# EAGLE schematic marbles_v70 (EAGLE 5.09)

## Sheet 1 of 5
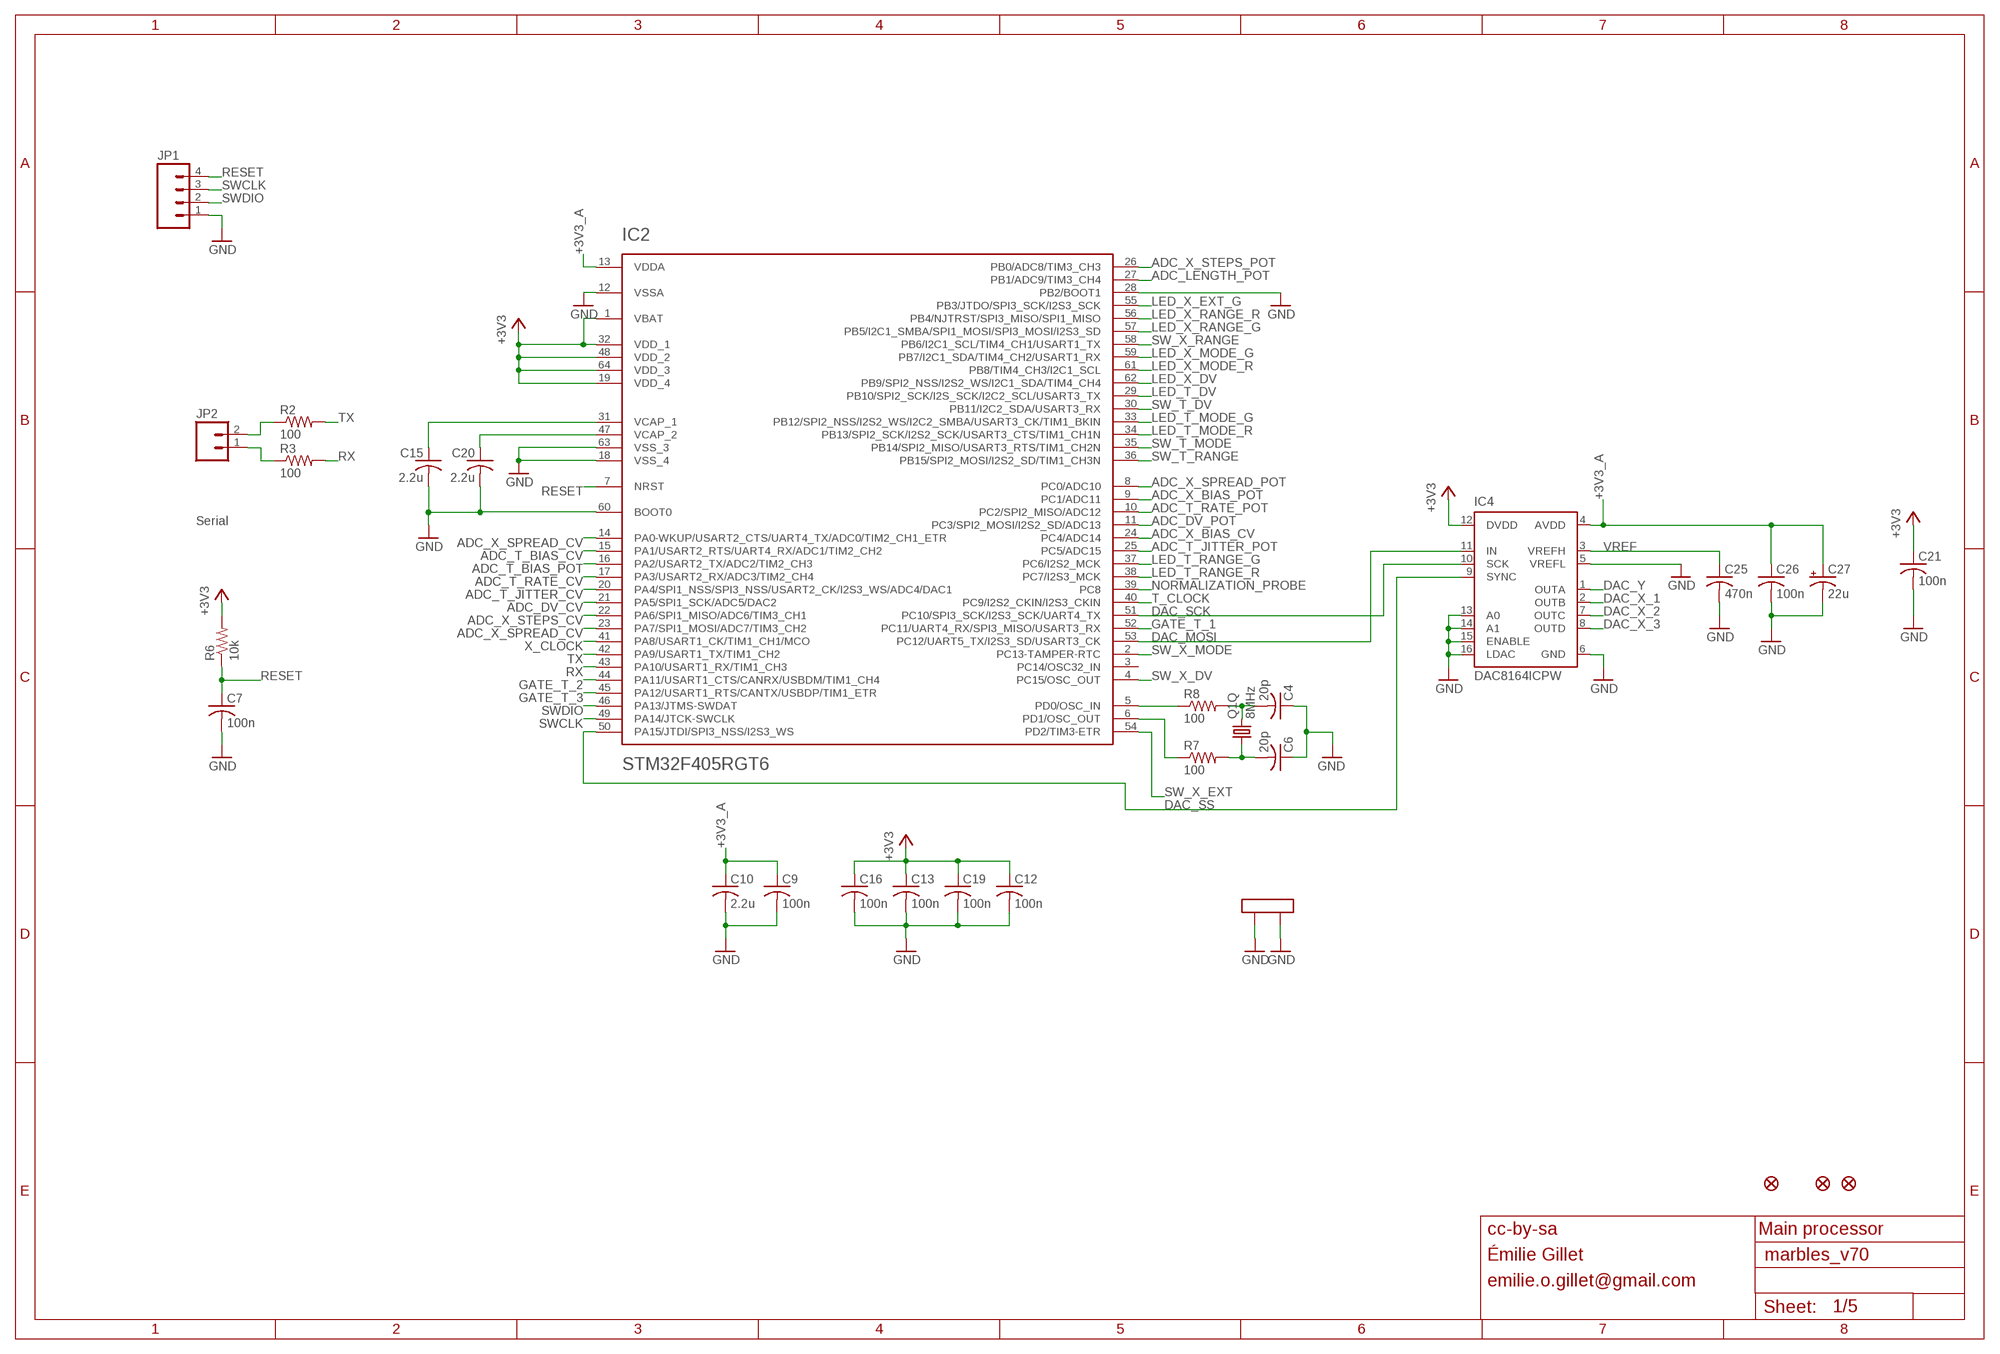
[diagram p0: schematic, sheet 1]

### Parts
C4  20p  C-USC0402  [C0402]
C6  20p  C-USC0402  [C0402]
C7  100n  C-USC0402  [C0402]
C9  100n  C-USC0402  [C0402]
C10  2.2u  C-USC0805  [C0805]
C12  100n  C-USC0402  [C0402]
C13  100n  C-USC0402  [C0402]
C15  2.2u  C-USC0805  [C0805]
C16  100n  C-USC0402  [C0402]
C19  100n  C-USC0402  [C0402]
C20  2.2u  C-USC0805  [C0805]
C21  100n  C-USC0402  [C0402]
C25  470n  C-USC0402  [C0402]
C26  100n  C-USC0402  [C0402]
C27  22u  CPOL-USC  [PANASONIC_C]
F1  FIDUCIAL1X2  [FIDUCIAL-1X2]
F2  FIDUCIAL1X2  [FIDUCIAL-1X2]
F3  FIDUCIAL1X2  [FIDUCIAL-1X2]
IC2  STM32F405RGT6  STM32F20X  [TQFP-10X10-64]
IC4  DAC8164ICPW  DAC8564  [SOP65P640X110-16N]
JP1  M04PTH  [1X04]
JP2  M02PTH  [1X02]
Q1  8MHz  CRYSTAL  [CTS406]
R2  100  R-US_R0402  [R0402]
R3  100  R-US_R0402  [R0402]
R6  10k  R-US_R0402  [R0402]
R7  100  R-US_R0402  [R0402]
R8  100  R-US_R0402  [R0402]

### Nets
+3V3: C12.1 C13.1 C16.1 C19.1 C21.1 IC2.1(VBAT) IC2.19(VDD_4) IC2.32(VDD_1) IC2.48(VDD_2) IC2.64(VDD_3) IC4.12(DVDD) R6.2 ; also sheet 3,5
+3V3_A: C9.1 C10.1 C26.1 C27.+ IC2.13(VDDA) IC4.4(AVDD) ; also sheet 2,3,5
ADC_DV_CV: IC2.21(PA5/SPI1_SCK/ADC5/DAC2) ; also sheet 3
ADC_DV_POT: IC2.11(PC3/SPI2_MOSI/I2S2_SD/ADC13) ; also sheet 2
ADC_LENGTH_POT: IC2.27(PB1/ADC9/TIM3_CH4) ; also sheet 2
ADC_T_BIAS_CV: IC2.15(PA1/USART2_RTS/UART4_RX/ADC1/TIM2_CH2) ; also sheet 3
ADC_T_BIAS_POT: IC2.16(PA2/USART2_TX/ADC2/TIM2_CH3) ; also sheet 2
ADC_T_JITTER_CV: IC2.20(PA4/SPI1_NSS/SPI3_NSS/USART2_CK/I2S3_WS/ADC4/DAC1) ; also sheet 3
ADC_T_JITTER_POT: IC2.25(PC5/ADC15) ; also sheet 2
ADC_T_RATE_CV: IC2.17(PA3/USART2_RX/ADC3/TIM2_CH4) ; also sheet 3
ADC_T_RATE_POT: IC2.10(PC2/SPI2_MISO/ADC12) ; also sheet 2
ADC_X_BIAS_CV: IC2.24(PC4/ADC14) ; also sheet 3
ADC_X_BIAS_POT: IC2.9(PC1/ADC11) ; also sheet 2
ADC_X_SPREAD_CV: IC2.14(PA0-WKUP/USART2_CTS/UART4_TX/ADC0/TIM2_CH1_ETR) IC2.23(PA7/SPI1_MOSI/ADC7/TIM3_CH2) ; also sheet 3
ADC_X_SPREAD_POT: IC2.8(PC0/ADC10) ; also sheet 2
ADC_X_STEPS_CV: IC2.22(PA6/SPI1_MISO/ADC6/TIM3_CH1) ; also sheet 3
ADC_X_STEPS_POT: IC2.26(PB0/ADC8/TIM3_CH3) ; also sheet 2
DAC_MOSI: IC2.53(PC12/UART5_TX/I2S3_SD/USART3_CK) IC4.11(IN)
DAC_SCK: IC2.51(PC10/SPI3_SCK/I2S3_SCK/UART4_TX) IC4.10(SCK)
DAC_SS: IC2.50(PA15/JTDI/SPI3_NSS/I2S3_WS) IC4.9(SYNC)
DAC_X_1: IC4.2(OUTB) ; also sheet 4
DAC_X_2: IC4.7(OUTC) ; also sheet 4
DAC_X_3: IC4.8(OUTD) ; also sheet 4
DAC_Y: IC4.1(OUTA) ; also sheet 4
GATE_T_1: IC2.52(PC11/UART4_RX/SPI3_MISO/USART3_RX) ; also sheet 4
GATE_T_2: IC2.44(PA11/USART1_CTS/CANRX/USBDM/TIM1_CH4) ; also sheet 4
GATE_T_3: IC2.45(PA12/USART1_RTS/CANTX/USBDP/TIM1_ETR) ; also sheet 4
GND: C4.1 C6.1 C7.2 C9.2 C10.2 C12.2 C13.2 C15.2 C16.2 C19.2 C20.2 C21.2 C25.2 C26.2 C27.- IC2.12(VSSA) IC2.18(VSS_4) IC2.28(PB2/BOOT1) IC2.60(BOOT0) IC2.63(VSS_3) IC4.5(VREFL) IC4.6(GND) IC4.13(A0) IC4.14(A1) IC4.15(ENABLE) IC4.16(LDAC) JP1.1 Q1.2(LID1) Q1.4(LID2) ; also sheet 2,3,4,5
LED_T_DV: IC2.29(PB10/SPI2_SCK/I2S_SCK/I2C2_SCL/USART3_TX) ; also sheet 2
LED_T_MODE_G: IC2.33(PB12/SPI2_NSS/I2S2_WS/I2C2_SMBA/USART3_CK/TIM1_BKIN) ; also sheet 2
LED_T_MODE_R: IC2.34(PB13/SPI2_SCK/I2S2_SCK/USART3_CTS/TIM1_CH1N) ; also sheet 2
LED_T_RANGE_G: IC2.37(PC6/I2S2_MCK) ; also sheet 2
LED_T_RANGE_R: IC2.38(PC7/I2S3_MCK) ; also sheet 2
LED_X_DV: IC2.62(PB9/SPI2_NSS/I2S2_WS/I2C1_SDA/TIM4_CH4) ; also sheet 2
LED_X_EXT_G: IC2.55(PB3/JTDO/SPI3_SCK/I2S3_SCK) ; also sheet 2
LED_X_MODE_G: IC2.59(PB7/I2C1_SDA/TIM4_CH2/USART1_RX) ; also sheet 2
LED_X_MODE_R: IC2.61(PB8/TIM4_CH3/I2C1_SCL) ; also sheet 2
LED_X_RANGE_G: IC2.57(PB5/I2C1_SMBA/SPI1_MOSI/SPI3_MOSI/I2S3_SD) ; also sheet 2
LED_X_RANGE_R: IC2.56(PB4/NJTRST/SPI3_MISO/SPI1_MISO) ; also sheet 2
N$7: IC2.6(PD1/OSC_OUT) R7.1
N$8: IC2.5(PD0/OSC_IN) R8.1
N$13: C20.1 IC2.47(VCAP_2)
N$19: C15.1 IC2.31(VCAP_1)
N$33: JP2.2 R2.1
N$51: JP2.1 R3.1
N$62: C4.2 Q1.3 R8.2
N$65: C6.2 Q1.1 R7.2
NORMALIZATION_PROBE: IC2.39(PC8) ; also sheet 3
RESET: C7.1 IC2.7(NRST) JP1.4 R6.1
RX: IC2.43(PA10/USART1_RX/TIM1_CH3) R3.2
SW_T_DV: IC2.30(PB11/I2C2_SDA/USART3_RX) ; also sheet 2
SW_T_MODE: IC2.35(PB14/SPI2_MISO/USART3_RTS/TIM1_CH2N) ; also sheet 2
SW_T_RANGE: IC2.36(PB15/SPI2_MOSI/I2S2_SD/TIM1_CH3N) ; also sheet 2
SW_X_DV: IC2.4(PC15/OSC_OUT) ; also sheet 2
SW_X_EXT: IC2.54(PD2/TIM3-ETR) ; also sheet 2
SW_X_MODE: IC2.2(PC13-TAMPER-RTC) ; also sheet 2
SW_X_RANGE: IC2.58(PB6/I2C1_SCL/TIM4_CH1/USART1_TX) ; also sheet 2
SWCLK: IC2.49(PA14/JTCK-SWCLK) JP1.3
SWDIO: IC2.46(PA13/JTMS-SWDAT) JP1.2
T_CLOCK: IC2.40(PC9/I2S2_CKIN/I2S3_CKIN) ; also sheet 3
TX: IC2.42(PA9/USART1_TX/TIM1_CH2) R2.2
VREF: C25.1 IC4.3(VREFH) ; also sheet 4
X_CLOCK: IC2.41(PA8/USART1_CK/TIM1_CH1/MCO) ; also sheet 3
Unconnected: IC2.3(PC14/OSC32_IN)

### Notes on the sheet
- Serial
- cc-by-sa | Main processor
- Émilie Gillet
- emilie.o.gillet@gmail.com

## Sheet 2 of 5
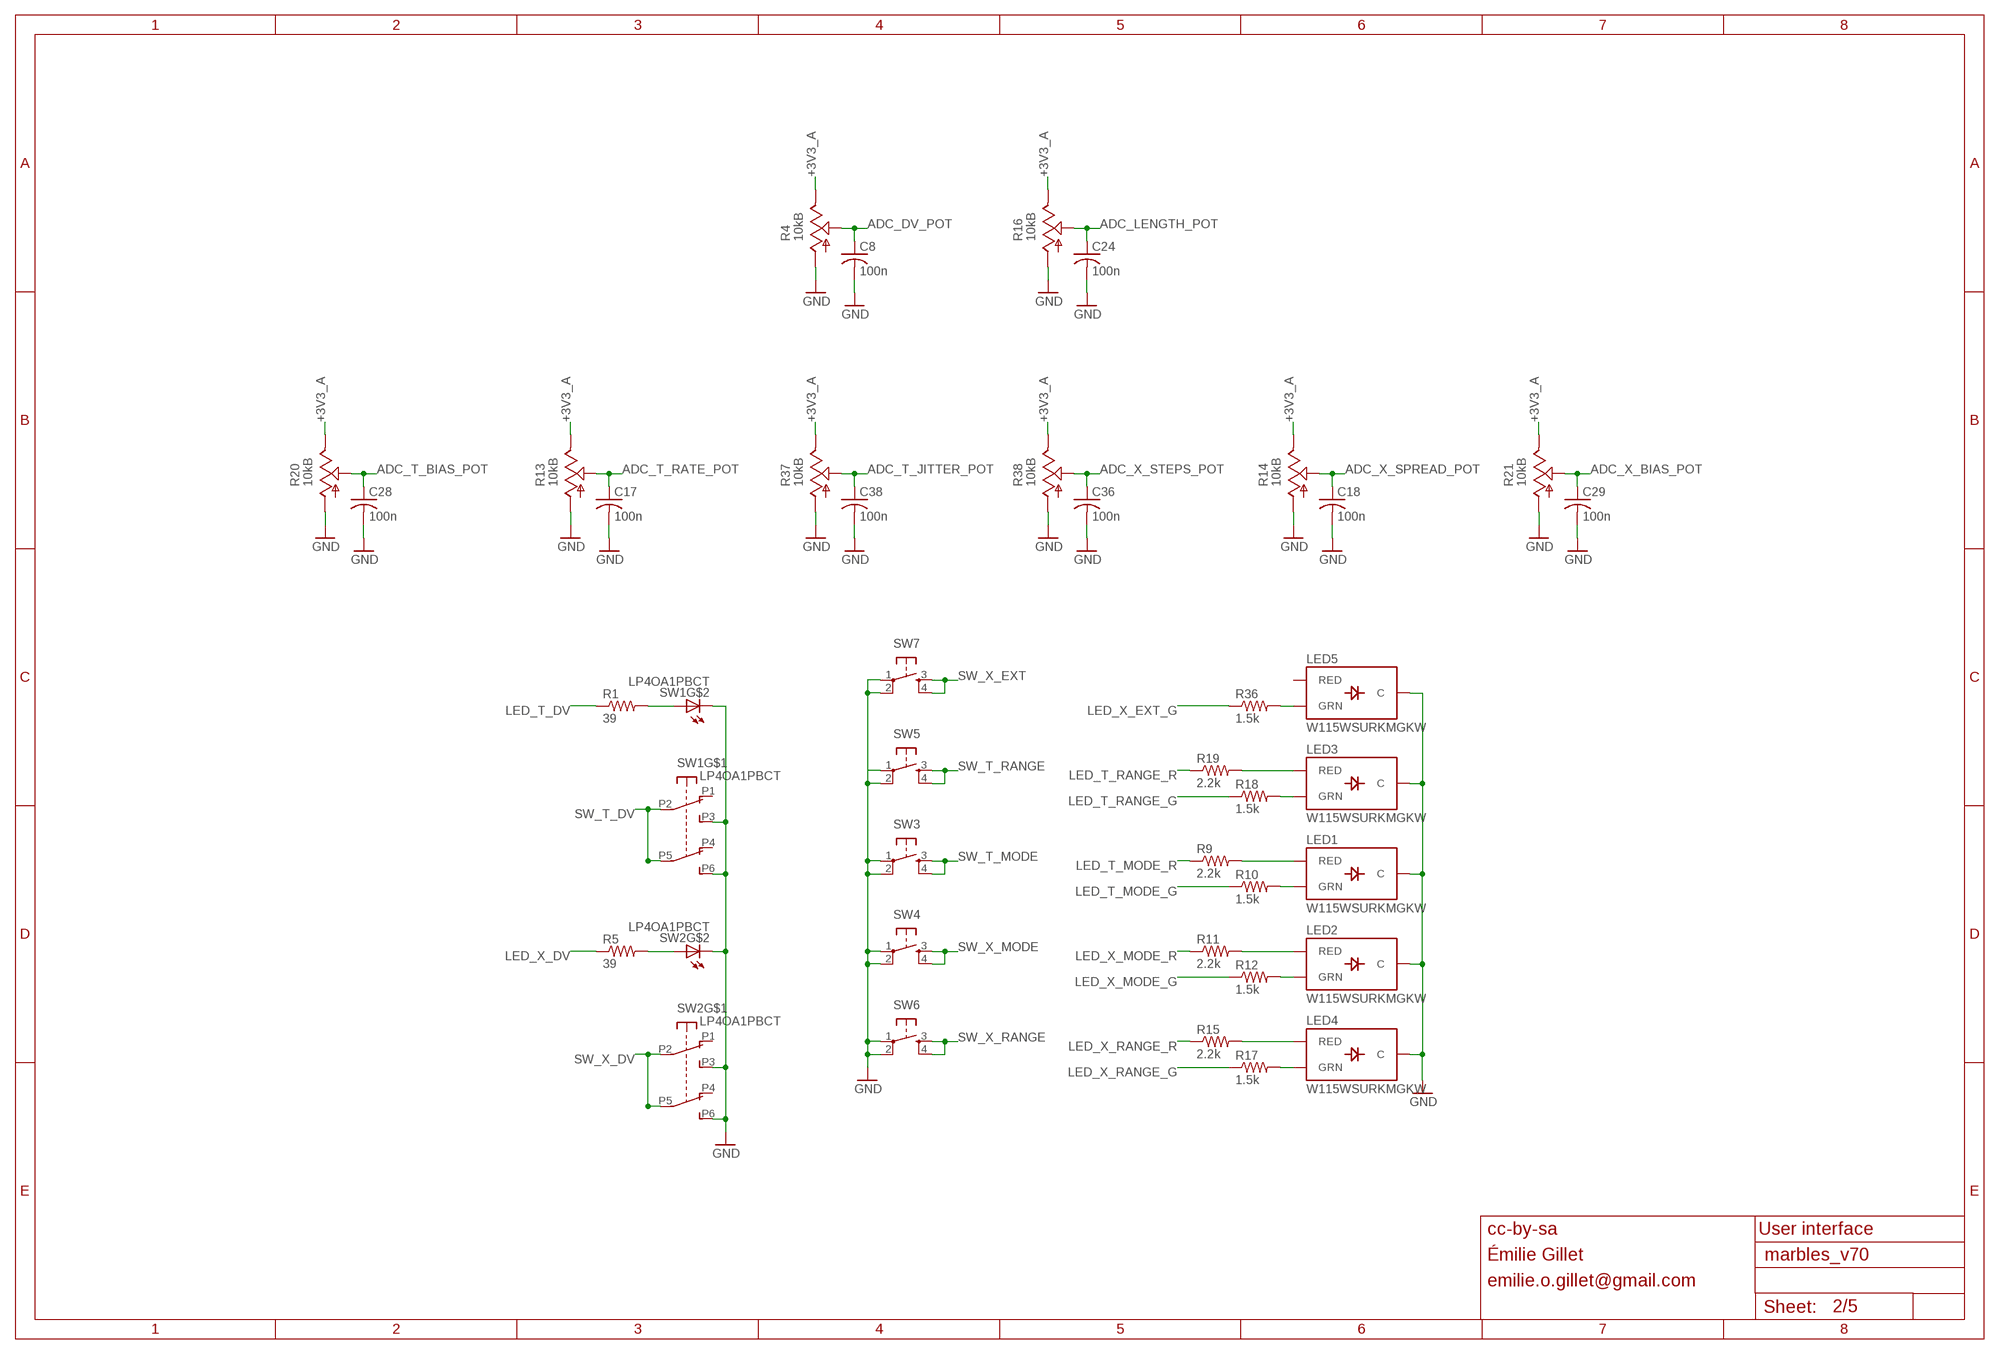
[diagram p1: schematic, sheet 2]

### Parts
C8  100n  C-USC0402  [C0402]
C17  100n  C-USC0402  [C0402]
C18  100n  C-USC0402  [C0402]
C24  100n  C-USC0402  [C0402]
C28  100n  C-USC0402  [C0402]
C29  100n  C-USC0402  [C0402]
C36  100n  C-USC0402  [C0402]
C38  100n  C-USC0402  [C0402]
LED1  W115WSURKMGKW  LED-BICOLOR-THROUGHHOLE2.54  [LED-BICOLOR-THROUGHHOLE-2.54]
LED2  W115WSURKMGKW  LED-BICOLOR-THROUGHHOLE2.54  [LED-BICOLOR-THROUGHHOLE-2.54]
LED3  W115WSURKMGKW  LED-BICOLOR-THROUGHHOLE2.54  [LED-BICOLOR-THROUGHHOLE-2.54]
LED4  W115WSURKMGKW  LED-BICOLOR-THROUGHHOLE2.54  [LED-BICOLOR-THROUGHHOLE-2.54]
LED5  W115WSURKMGKW  LED-BICOLOR-THROUGHHOLE2.54  [LED-BICOLOR-THROUGHHOLE-2.54]
R1  39  R-US_R0402  [R0402]
R4  10kB  POT_USVERTICAL_PS  [ALPS_POT_VERTICAL_PS]
R5  39  R-US_R0402  [R0402]
R9  2.2k  R-US_R0402  [R0402]
R10  1.5k  R-US_R0402  [R0402]
R11  2.2k  R-US_R0402  [R0402]
R12  1.5k  R-US_R0402  [R0402]
R13  10kB  POT_USVERTICAL_PS  [ALPS_POT_VERTICAL_PS]
R14  10kB  POT_USVERTICAL_PS  [ALPS_POT_VERTICAL_PS]
R15  2.2k  R-US_R0402  [R0402]
R16  10kB  POT_USVERTICAL_PS  [ALPS_POT_VERTICAL_PS]
R17  1.5k  R-US_R0402  [R0402]
R18  1.5k  R-US_R0402  [R0402]
R19  2.2k  R-US_R0402  [R0402]
R20  10kB  POT_USVERTICAL_PS  [ALPS_POT_VERTICAL_PS]
R21  10kB  POT_USVERTICAL_PS  [ALPS_POT_VERTICAL_PS]
R36  1.5k  R-US_R0402  [R0402]
R37  10kB  POT_USVERTICAL_PS  [ALPS_POT_VERTICAL_PS]
R38  10kB  POT_USVERTICAL_PS  [ALPS_POT_VERTICAL_PS]
SW1  LP4OA1PBCT  [LP4OA1PBCT]
SW2  LP4OA1PBCT  [LP4OA1PBCT]
SW3  TAC_SWITCHPTH  [TACTILE-PTH]
SW4  TAC_SWITCHPTH  [TACTILE-PTH]
SW5  TAC_SWITCHPTH  [TACTILE-PTH]
SW6  TAC_SWITCHPTH  [TACTILE-PTH]
SW7  TAC_SWITCHPTH  [TACTILE-PTH]

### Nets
+3V3_A: R4.P$1(E) R13.P$1(E) R14.P$1(E) R16.P$1(E) R20.P$1(E) R21.P$1(E) R37.P$1(E) R38.P$1(E) ; also sheet 1,3,5
ADC_DV_POT: C8.1 R4.P$2(S) ; also sheet 1
ADC_LENGTH_POT: C24.1 R16.P$2(S) ; also sheet 1
ADC_T_BIAS_POT: C28.1 R20.P$2(S) ; also sheet 1
ADC_T_JITTER_POT: C38.1 R37.P$2(S) ; also sheet 1
ADC_T_RATE_POT: C17.1 R13.P$2(S) ; also sheet 1
ADC_X_BIAS_POT: C29.1 R21.P$2(S) ; also sheet 1
ADC_X_SPREAD_POT: C18.1 R14.P$2(S) ; also sheet 1
ADC_X_STEPS_POT: C36.1 R38.P$2(S) ; also sheet 1
GND: C8.2 C17.2 C18.2 C24.2 C28.2 C29.2 C36.2 C38.2 LED1.2(C) LED2.2(C) LED3.2(C) LED4.2(C) LED5.2(C) R4.P$3(A) R13.P$3(A) R14.P$3(A) R16.P$3(A) R20.P$3(A) R21.P$3(A) R37.P$3(A) R38.P$3(A) SW1.L2 SW1.P3(A3) SW1.P6(B3) SW2.L2 SW2.P3(A3) SW2.P6(B3) SW3.1 SW3.2 SW4.1 SW4.2 SW5.1 SW5.2 SW6.1 SW6.2 SW7.1 SW7.2 ; also sheet 1,3,4,5
LED_T_DV: R1.1 ; also sheet 1
LED_T_MODE_G: R10.1 ; also sheet 1
LED_T_MODE_R: R9.1 ; also sheet 1
LED_T_RANGE_G: R18.1 ; also sheet 1
LED_T_RANGE_R: R19.1 ; also sheet 1
LED_X_DV: R5.1 ; also sheet 1
LED_X_EXT_G: R36.1 ; also sheet 1
LED_X_MODE_G: R12.1 ; also sheet 1
LED_X_MODE_R: R11.1 ; also sheet 1
LED_X_RANGE_G: R17.1 ; also sheet 1
LED_X_RANGE_R: R15.1 ; also sheet 1
N$1: R1.2 SW1.L1
N$2: R5.2 SW2.L1
N$9: LED3.3(RED) R19.2
N$12: LED3.1(GRN) R18.2
N$16: LED1.3(RED) R9.2
N$18: LED2.3(RED) R11.2
N$20: LED2.1(GRN) R12.2
N$21: LED4.3(RED) R15.2
N$22: LED1.1(GRN) R10.2
N$23: LED4.1(GRN) R17.2
N$42: LED5.1(GRN) R36.2
SW_T_DV: SW1.P2(A2) SW1.P5(B2) ; also sheet 1
SW_T_MODE: SW3.3 SW3.4 ; also sheet 1
SW_T_RANGE: SW5.3 SW5.4 ; also sheet 1
SW_X_DV: SW2.P2(A2) SW2.P5(B2) ; also sheet 1
SW_X_EXT: SW7.3 SW7.4 ; also sheet 1
SW_X_MODE: SW4.3 SW4.4 ; also sheet 1
SW_X_RANGE: SW6.3 SW6.4 ; also sheet 1
Unconnected: LED5.3(RED) SW1.P1(A1) SW1.P4(B1) SW2.P1(A1) SW2.P4(B1)

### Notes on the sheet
- cc-by-sa | User interface
- Émilie Gillet
- emilie.o.gillet@gmail.com

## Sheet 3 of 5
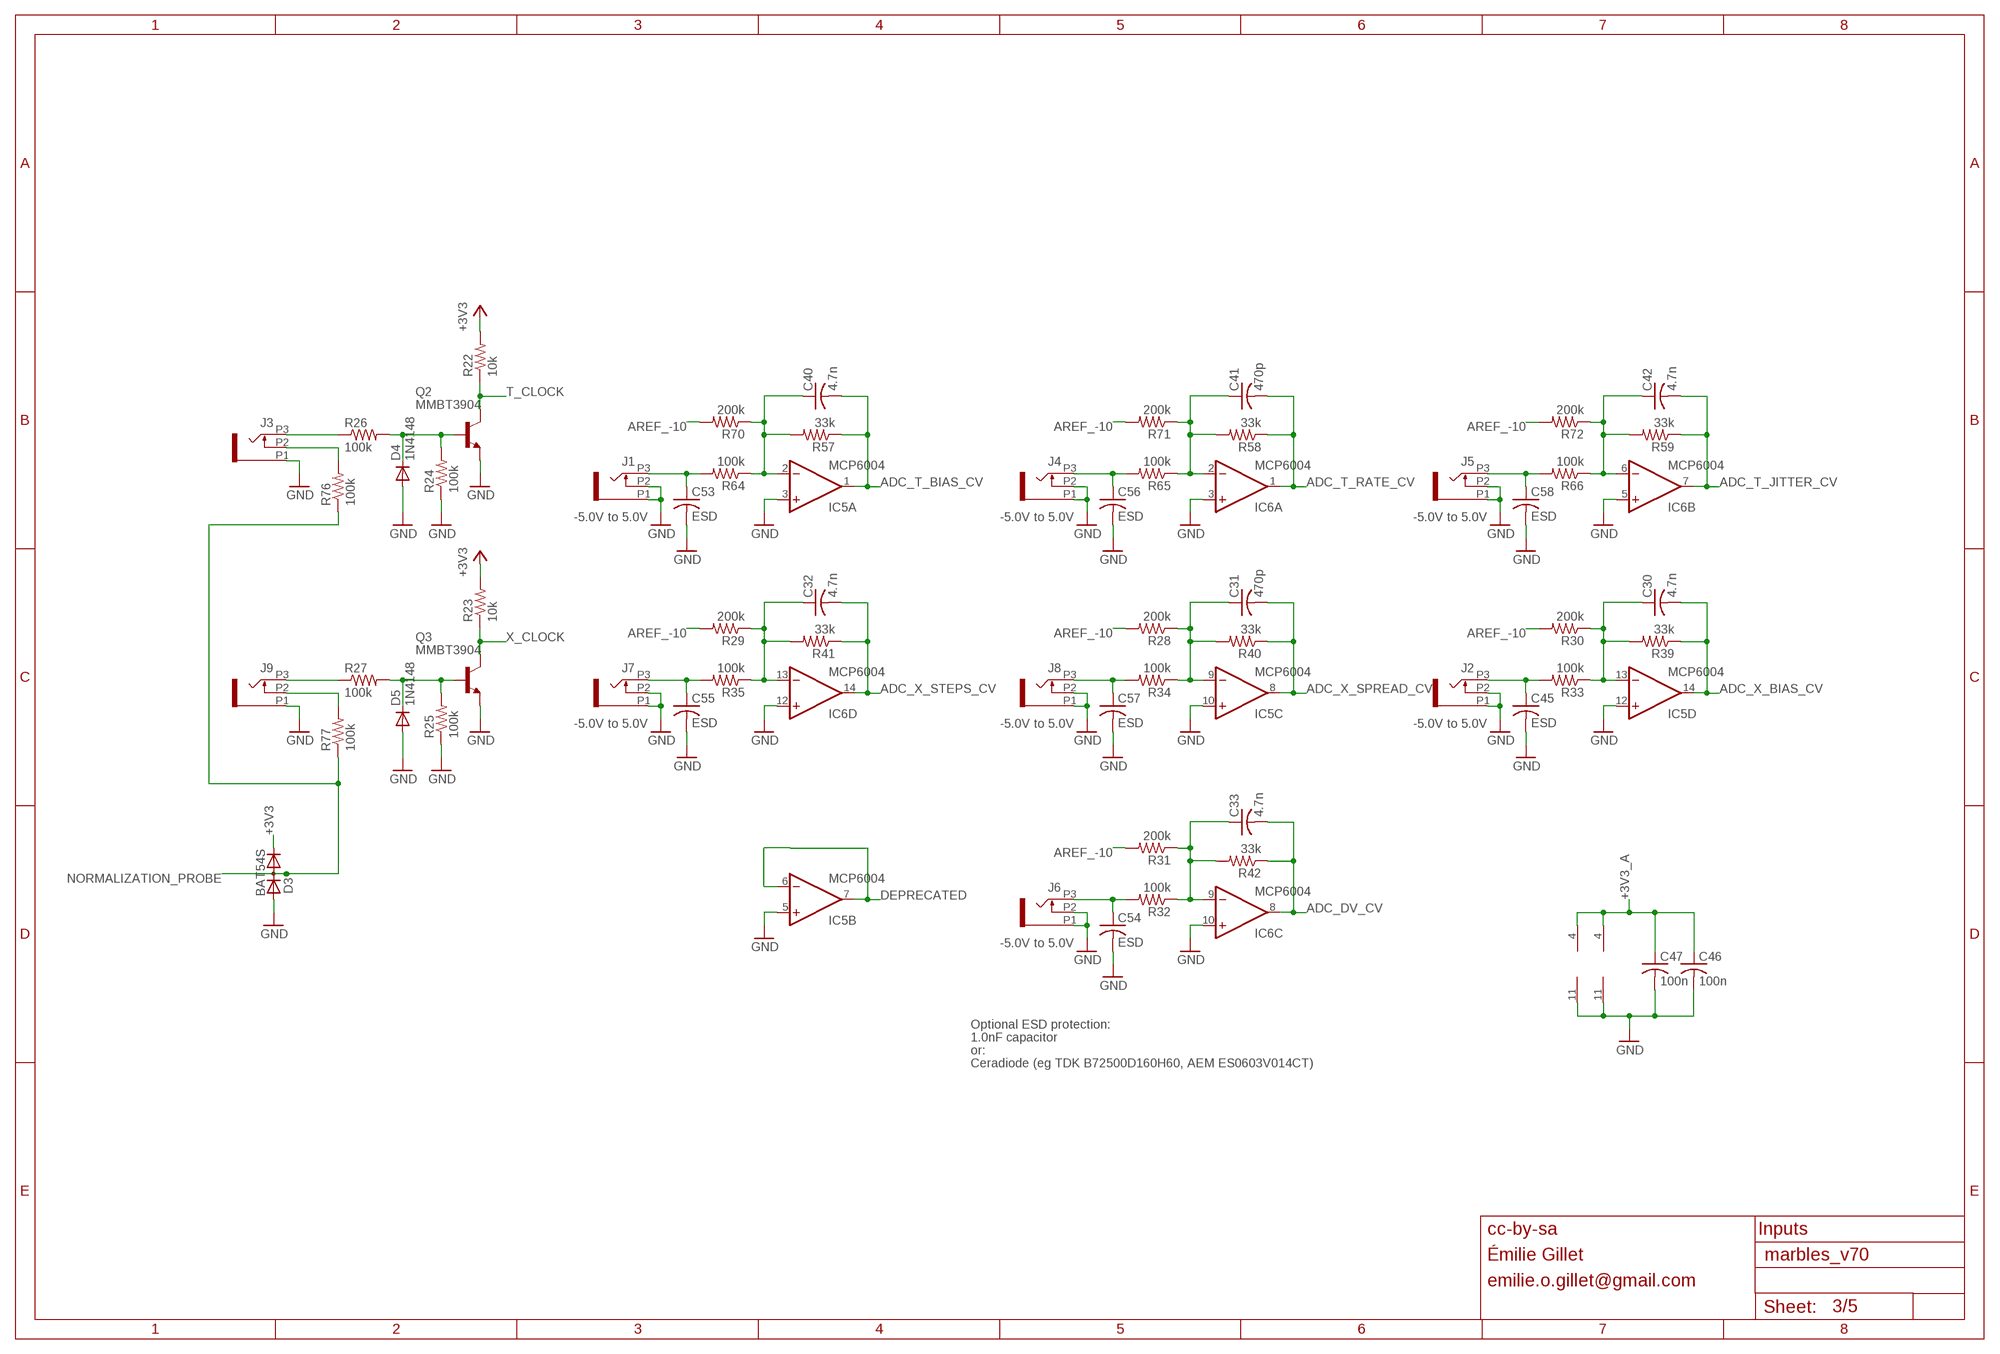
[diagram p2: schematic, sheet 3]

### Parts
C30  4.7n  C-USC0402  [C0402]
C31  470p  C-USC0402  [C0402]
C32  4.7n  C-USC0402  [C0402]
C33  4.7n  C-USC0402  [C0402]
C40  4.7n  C-USC0402  [C0402]
C41  470p  C-USC0402  [C0402]
C42  4.7n  C-USC0402  [C0402]
C45  ESD  C-USC0603  [C0603]
C46  100n  C-USC0402  [C0402]
C47  100n  C-USC0402  [C0402]
C53  ESD  C-USC0603  [C0603]
C54  ESD  C-USC0603  [C0603]
C55  ESD  C-USC0603  [C0603]
C56  ESD  C-USC0603  [C0603]
C57  ESD  C-USC0603  [C0603]
C58  ESD  C-USC0603  [C0603]
D3  BAT54S  DIODE_2CACA-SOT23  [SOT23]
D4  1N4148  DIODE-SOD523  [SOD523]
D5  1N4148  DIODE-SOD523  [SOD523]
IC5  MCP6004  TL074PW  [TSSOP14_065]
IC6  MCP6004  TL074PW  [TSSOP14_065]
J1  PJ301_THONKICONN6  [WQP_PJ_301M6]
J2  PJ301_THONKICONN6  [WQP_PJ_301M6]
J3  PJ301_THONKICONN6  [WQP_PJ_301M6]
J4  PJ301_THONKICONN6  [WQP_PJ_301M6]
J5  PJ301_THONKICONN6  [WQP_PJ_301M6]
J6  PJ301_THONKICONN6  [WQP_PJ_301M6]
J7  PJ301_THONKICONN6  [WQP_PJ_301M6]
J8  PJ301_THONKICONN6  [WQP_PJ_301M6]
J9  PJ301_THONKICONN6  [WQP_PJ_301M6]
Q2  MMBT3904  MMBT3904LT1-NPN-SOT23-BEC  [SOT23-BEC]
Q3  MMBT3904  MMBT3904LT1-NPN-SOT23-BEC  [SOT23-BEC]
R22  10k  R-US_R0402  [R0402]
R23  10k  R-US_R0402  [R0402]
R24  100k  R-US_R0402  [R0402]
R25  100k  R-US_R0402  [R0402]
R26  100k  R-US_R0402  [R0402]
R27  100k  R-US_R0402  [R0402]
R28  200k  R-US_R0402  [R0402]
R29  200k  R-US_R0402  [R0402]
R30  200k  R-US_R0402  [R0402]
R31  200k  R-US_R0402  [R0402]
R32  100k  R-US_R0402  [R0402]
R33  100k  R-US_R0402  [R0402]
R34  100k  R-US_R0402  [R0402]
R35  100k  R-US_R0402  [R0402]
R39  33k  R-US_R0402  [R0402]
R40  33k  R-US_R0402  [R0402]
R41  33k  R-US_R0402  [R0402]
R42  33k  R-US_R0402  [R0402]
R57  33k  R-US_R0402  [R0402]
R58  33k  R-US_R0402  [R0402]
R59  33k  R-US_R0402  [R0402]
R64  100k  R-US_R0402  [R0402]
R65  100k  R-US_R0402  [R0402]
R66  100k  R-US_R0402  [R0402]
R70  200k  R-US_R0402  [R0402]
R71  200k  R-US_R0402  [R0402]
R72  200k  R-US_R0402  [R0402]
R76  100k  R-US_R0402  [R0402]
R77  100k  R-US_R0402  [R0402]

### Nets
+3V3: D3.2(C) R22.2 R23.2 ; also sheet 1,5
+3V3_A: C46.1 C47.1 IC5.4(P:V+) IC6.4(P:V+) ; also sheet 1,2,5
ADC_DV_CV: C33.2 IC6.8(C:OUT) R42.1 ; also sheet 1
ADC_T_BIAS_CV: C40.2 IC5.1(A:OUT) R57.1 ; also sheet 1
ADC_T_JITTER_CV: C42.2 IC6.7(B:OUT) R59.1 ; also sheet 1
ADC_T_RATE_CV: C41.2 IC6.1(A:OUT) R58.1 ; also sheet 1
ADC_X_BIAS_CV: C30.2 IC5.14(D:OUT) R39.1 ; also sheet 1
ADC_X_SPREAD_CV: C31.2 IC5.8(C:OUT) R40.1 ; also sheet 1
ADC_X_STEPS_CV: C32.2 IC6.14(D:OUT) R41.1 ; also sheet 1
AREF_-10: R28.2 R29.2 R30.2 R31.2 R70.2 R71.2 R72.2 ; also sheet 5
DEPRECATED: IC5.6(B:-IN) IC5.7(B:OUT)
GND: C45.2 C46.2 C47.2 C53.2 C54.2 C55.2 C56.2 C57.2 C58.2 D3.1(A) D4.A D5.A IC5.3(A:+IN) IC5.5(B:+IN) IC5.10(C:+IN) IC5.11(P:V-) IC5.12(D:+IN) IC6.3(A:+IN) IC6.5(B:+IN) IC6.10(C:+IN) IC6.11(P:V-) IC6.12(D:+IN) J1.P1 J1.P2 J2.P1 J2.P2 J3.P1 J4.P1 J4.P2 J5.P1 J5.P2 J6.P1 J6.P2 J7.P1 J7.P2 J8.P1 J8.P2 J9.P1 Q2.E Q3.E R24.1 R25.1 ; also sheet 1,2,4,5
MORPH_IN: C53.1 J1.P3 R64.2
MORPH_IN1: C55.1 J7.P3 R35.2
MORPH_IN3: C56.1 J4.P3 R65.2
MORPH_IN4: C57.1 J8.P3 R34.2
MORPH_IN5: C54.1 J6.P3 R32.2
MORPH_IN6: C58.1 J5.P3 R66.2
MORPH_IN7: C45.1 J2.P3 R33.2
N$5: C41.1 IC6.2(A:-IN) R58.2 R65.1 R71.1
N$11: C40.1 IC5.2(A:-IN) R57.2 R64.1 R70.1
N$15: C42.1 IC6.6(B:-IN) R59.2 R66.1 R72.1
N$17: C31.1 IC5.9(C:-IN) R28.1 R34.1 R40.2
N$25: C30.1 IC5.13(D:-IN) R30.1 R33.1 R39.2
N$27: C32.1 IC6.13(D:-IN) R29.1 R35.1 R41.2
N$31: C33.1 IC6.9(C:-IN) R31.1 R32.1 R42.2
N$36: J9.P3 R27.1
N$46: J9.P2 R77.2
N$47: J3.P2 R76.2
N$50: D4.C Q2.B R24.2 R26.2
N$52: D5.C Q3.B R25.2 R27.2
N$57: J3.P3 R26.1
NORMALIZATION_PROBE: D3.3(AC) R76.1 R77.1 ; also sheet 1
T_CLOCK: Q2.C R22.1 ; also sheet 1
X_CLOCK: Q3.C R23.1 ; also sheet 1

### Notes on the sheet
- -5.0V to 5.0V | -5.0V to 5.0V | -5.0V to 5.0V
- -5.0V to 5.0V | -5.0V to 5.0V | -5.0V to 5.0V
- -5.0V to 5.0V
- Optional ESD protection:
- 1.0nF capacitor
- or:
- Ceradiode (eg TDK B72500D160H60, AEM ES0603V014CT)
- cc-by-sa | Inputs
- Émilie Gillet
- emilie.o.gillet@gmail.com

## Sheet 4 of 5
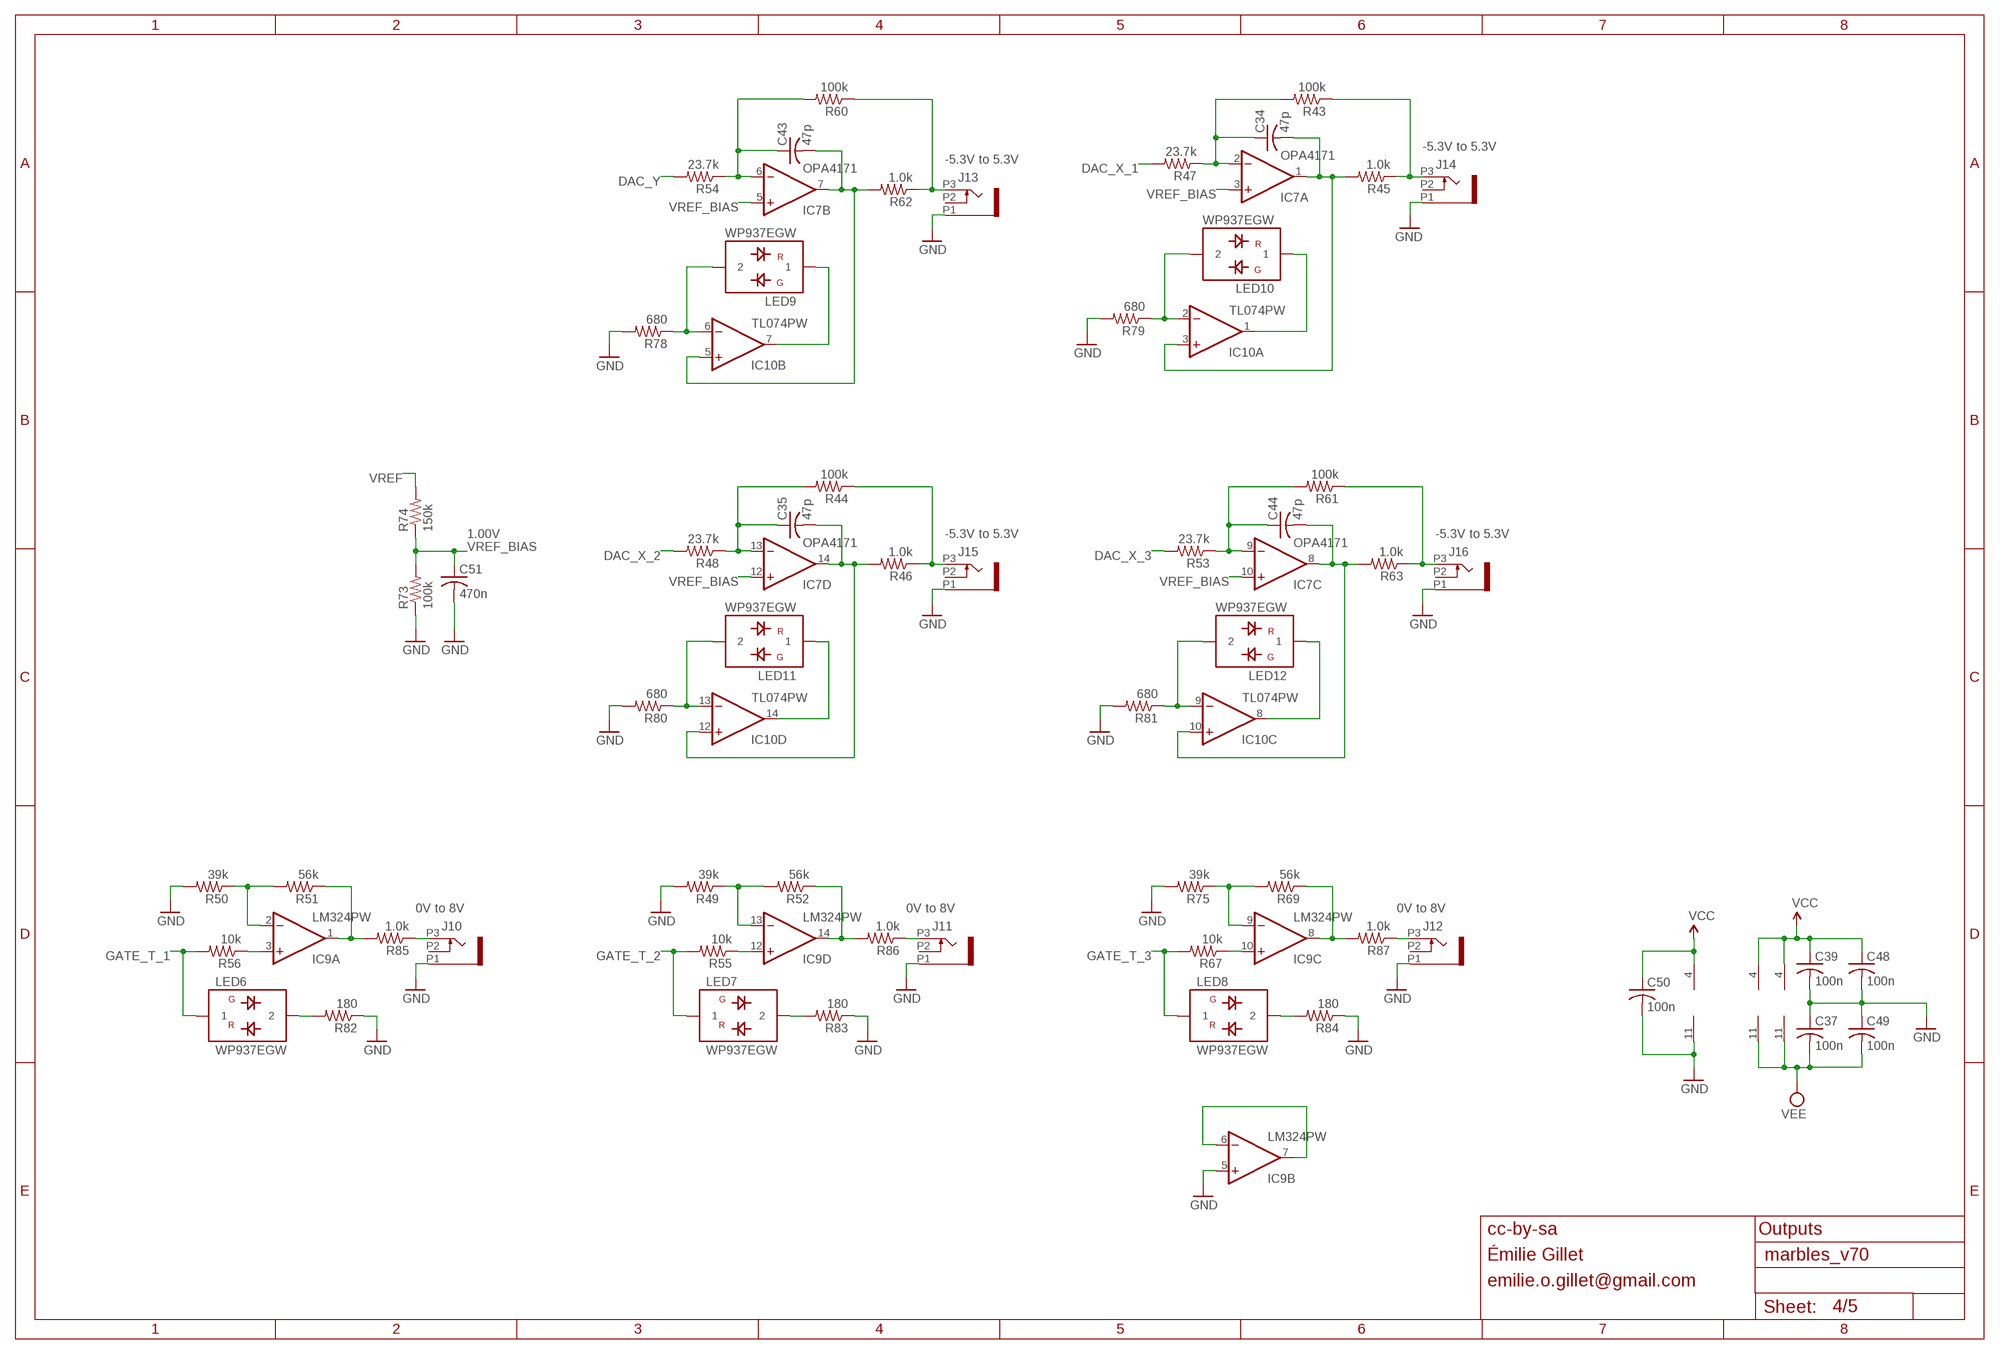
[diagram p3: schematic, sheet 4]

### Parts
C34  47p  C-USC0402  [C0402]
C35  47p  C-USC0402  [C0402]
C37  100n  C-USC0402  [C0402]
C39  100n  C-USC0402  [C0402]
C43  47p  C-USC0402  [C0402]
C44  47p  C-USC0402  [C0402]
C48  100n  C-USC0402  [C0402]
C49  100n  C-USC0402  [C0402]
C50  100n  C-USC0402  [C0402]
C51  470n  C-USC0402  [C0402]
IC7  OPA4171  TL074PW  [TSSOP14_065]
IC9  LM324PW  TL074PW  [TSSOP14_065]
IC10  TL074PW  [TSSOP14_065]
J10  PJ301_THONKICONN6  [WQP_PJ_301M6]
J11  PJ301_THONKICONN6  [WQP_PJ_301M6]
J12  PJ301_THONKICONN6  [WQP_PJ_301M6]
J13  PJ301_THONKICONN6  [WQP_PJ_301M6]
J14  PJ301_THONKICONN6  [WQP_PJ_301M6]
J15  PJ301_THONKICONN6  [WQP_PJ_301M6]
J16  PJ301_THONKICONN6  [WQP_PJ_301M6]
LED6  WP937EGW  LED-BICOLOR-SHARED-THROUGHHOLE  [LED3MM]
LED7  WP937EGW  LED-BICOLOR-SHARED-THROUGHHOLE  [LED3MM]
LED8  WP937EGW  LED-BICOLOR-SHARED-THROUGHHOLE  [LED3MM]
LED9  WP937EGW  LED-BICOLOR-SHARED-THROUGHHOLE  [LED3MM]
LED10  WP937EGW  LED-BICOLOR-SHARED-THROUGHHOLE  [LED3MM]
LED11  WP937EGW  LED-BICOLOR-SHARED-THROUGHHOLE  [LED3MM]
LED12  WP937EGW  LED-BICOLOR-SHARED-THROUGHHOLE  [LED3MM]
R43  100k  R-US_R0402  [R0402]
R44  100k  R-US_R0402  [R0402]
R45  1.0k  R-US_R0603  [R0603]
R46  1.0k  R-US_R0603  [R0603]
R47  23.7k  R-US_R0402  [R0402]
R48  23.7k  R-US_R0402  [R0402]
R49  39k  R-US_R0402  [R0402]
R50  39k  R-US_R0402  [R0402]
R51  56k  R-US_R0402  [R0402]
R52  56k  R-US_R0402  [R0402]
R53  23.7k  R-US_R0402  [R0402]
R54  23.7k  R-US_R0402  [R0402]
R55  10k  R-US_R0402  [R0402]
R56  10k  R-US_R0402  [R0402]
R60  100k  R-US_R0402  [R0402]
R61  100k  R-US_R0402  [R0402]
R62  1.0k  R-US_R0603  [R0603]
R63  1.0k  R-US_R0603  [R0603]
R67  10k  R-US_R0402  [R0402]
R69  56k  R-US_R0402  [R0402]
R73  100k  R-US_R0402  [R0402]
R74  150k  R-US_R0402  [R0402]
R75  39k  R-US_R0402  [R0402]
R78  680  R-US_R0402  [R0402]
R79  680  R-US_R0402  [R0402]
R80  680  R-US_R0402  [R0402]
R81  680  R-US_R0402  [R0402]
R82  180  R-US_R0402  [R0402]
R83  180  R-US_R0402  [R0402]
R84  180  R-US_R0402  [R0402]
R85  1.0k  R-US_R0603  [R0603]
R86  1.0k  R-US_R0603  [R0603]
R87  1.0k  R-US_R0603  [R0603]

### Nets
DAC_X_1: R47.2 ; also sheet 1
DAC_X_2: R48.2 ; also sheet 1
DAC_X_3: R53.2 ; also sheet 1
DAC_Y: R54.2 ; also sheet 1
GATE_T_1: LED6.1 R56.2 ; also sheet 1
GATE_T_2: LED7.1 R55.2 ; also sheet 1
GATE_T_3: LED8.1 R67.2 ; also sheet 1
GND: C37.1 C39.2 C48.2 C49.1 C50.2 C51.2 IC9.5(B:+IN) IC9.11(P:V-) J10.P1 J11.P1 J12.P1 J13.P1 J14.P1 J15.P1 J16.P1 R49.2 R50.2 R73.1 R75.2 R78.2 R79.2 R80.2 R81.2 R82.1 R83.1 R84.1 ; also sheet 1,2,3,5
N$3: IC9.12(D:+IN) R55.1
N$14: IC9.1(A:OUT) R51.1 R85.2
N$24: J10.P3 R85.1
N$26: IC9.2(A:-IN) R50.1 R51.2
N$28: LED6.2 R82.2
N$29: IC9.3(A:+IN) R56.1
N$30: IC9.6(B:-IN) IC9.7(B:OUT)
N$34: IC9.14(D:OUT) R52.1 R86.2
N$35: IC9.13(D:-IN) R49.1 R52.2
N$37: IC9.10(C:+IN) R67.1
N$38: IC9.8(C:OUT) R69.1 R87.2
N$39: J11.P3 R86.1
N$40: J12.P3 R87.1
N$41: IC9.9(C:-IN) R69.2 R75.1
N$44: LED7.2 R83.2
N$45: C43.2 IC7.7(B:OUT) IC10.5(B:+IN) R62.2
N$48: LED8.2 R84.2
N$49: J15.P3 R44.1 R46.1
N$53: J13.P3 R60.1 R62.1
N$54: C35.1 IC7.13(D:-IN) R44.2 R48.1
N$58: J16.P3 R61.1 R63.1
N$59: C44.1 IC7.9(C:-IN) R53.1 R61.2
N$60: C34.1 IC7.2(A:-IN) R43.2 R47.1
N$61: C43.1 IC7.6(B:-IN) R54.1 R60.2
N$63: J14.P3 R43.1 R45.1
N$67: IC10.6(B:-IN) LED9.2 R78.1
N$68: IC10.7(B:OUT) LED9.1
N$70: C34.2 IC7.1(A:OUT) IC10.3(A:+IN) R45.2
N$71: IC10.2(A:-IN) LED10.2 R79.1
N$72: IC10.1(A:OUT) LED10.1
N$73: C35.2 IC7.14(D:OUT) IC10.12(D:+IN) R46.2
N$74: IC10.13(D:-IN) LED11.2 R80.1
N$75: IC10.14(D:OUT) LED11.1
N$76: C44.2 IC7.8(C:OUT) IC10.10(C:+IN) R63.2
N$77: IC10.9(C:-IN) LED12.2 R81.1
N$78: IC10.8(C:OUT) LED12.1
VCC: C39.1 C48.1 C50.1 IC7.4(P:V+) IC9.4(P:V+) IC10.4(P:V+) ; also sheet 5
VEE: C37.2 C49.2 IC7.11(P:V-) IC10.11(P:V-) ; also sheet 5
VREF: R74.2 ; also sheet 1
VREF_BIAS: C51.1 IC7.3(A:+IN) IC7.5(B:+IN) IC7.10(C:+IN) IC7.12(D:+IN) R73.2 R74.1
Unconnected: J10.P2 J11.P2 J12.P2 J13.P2 J14.P2 J15.P2 J16.P2

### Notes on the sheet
- -5.3V to 5.3V
- -5.3V to 5.3V
- 1.00V | -5.3V to 5.3V | -5.3V to 5.3V
- 0V to 8V | 0V to 8V | 0V to 8V
- cc-by-sa | Outputs
- Émilie Gillet
- emilie.o.gillet@gmail.com

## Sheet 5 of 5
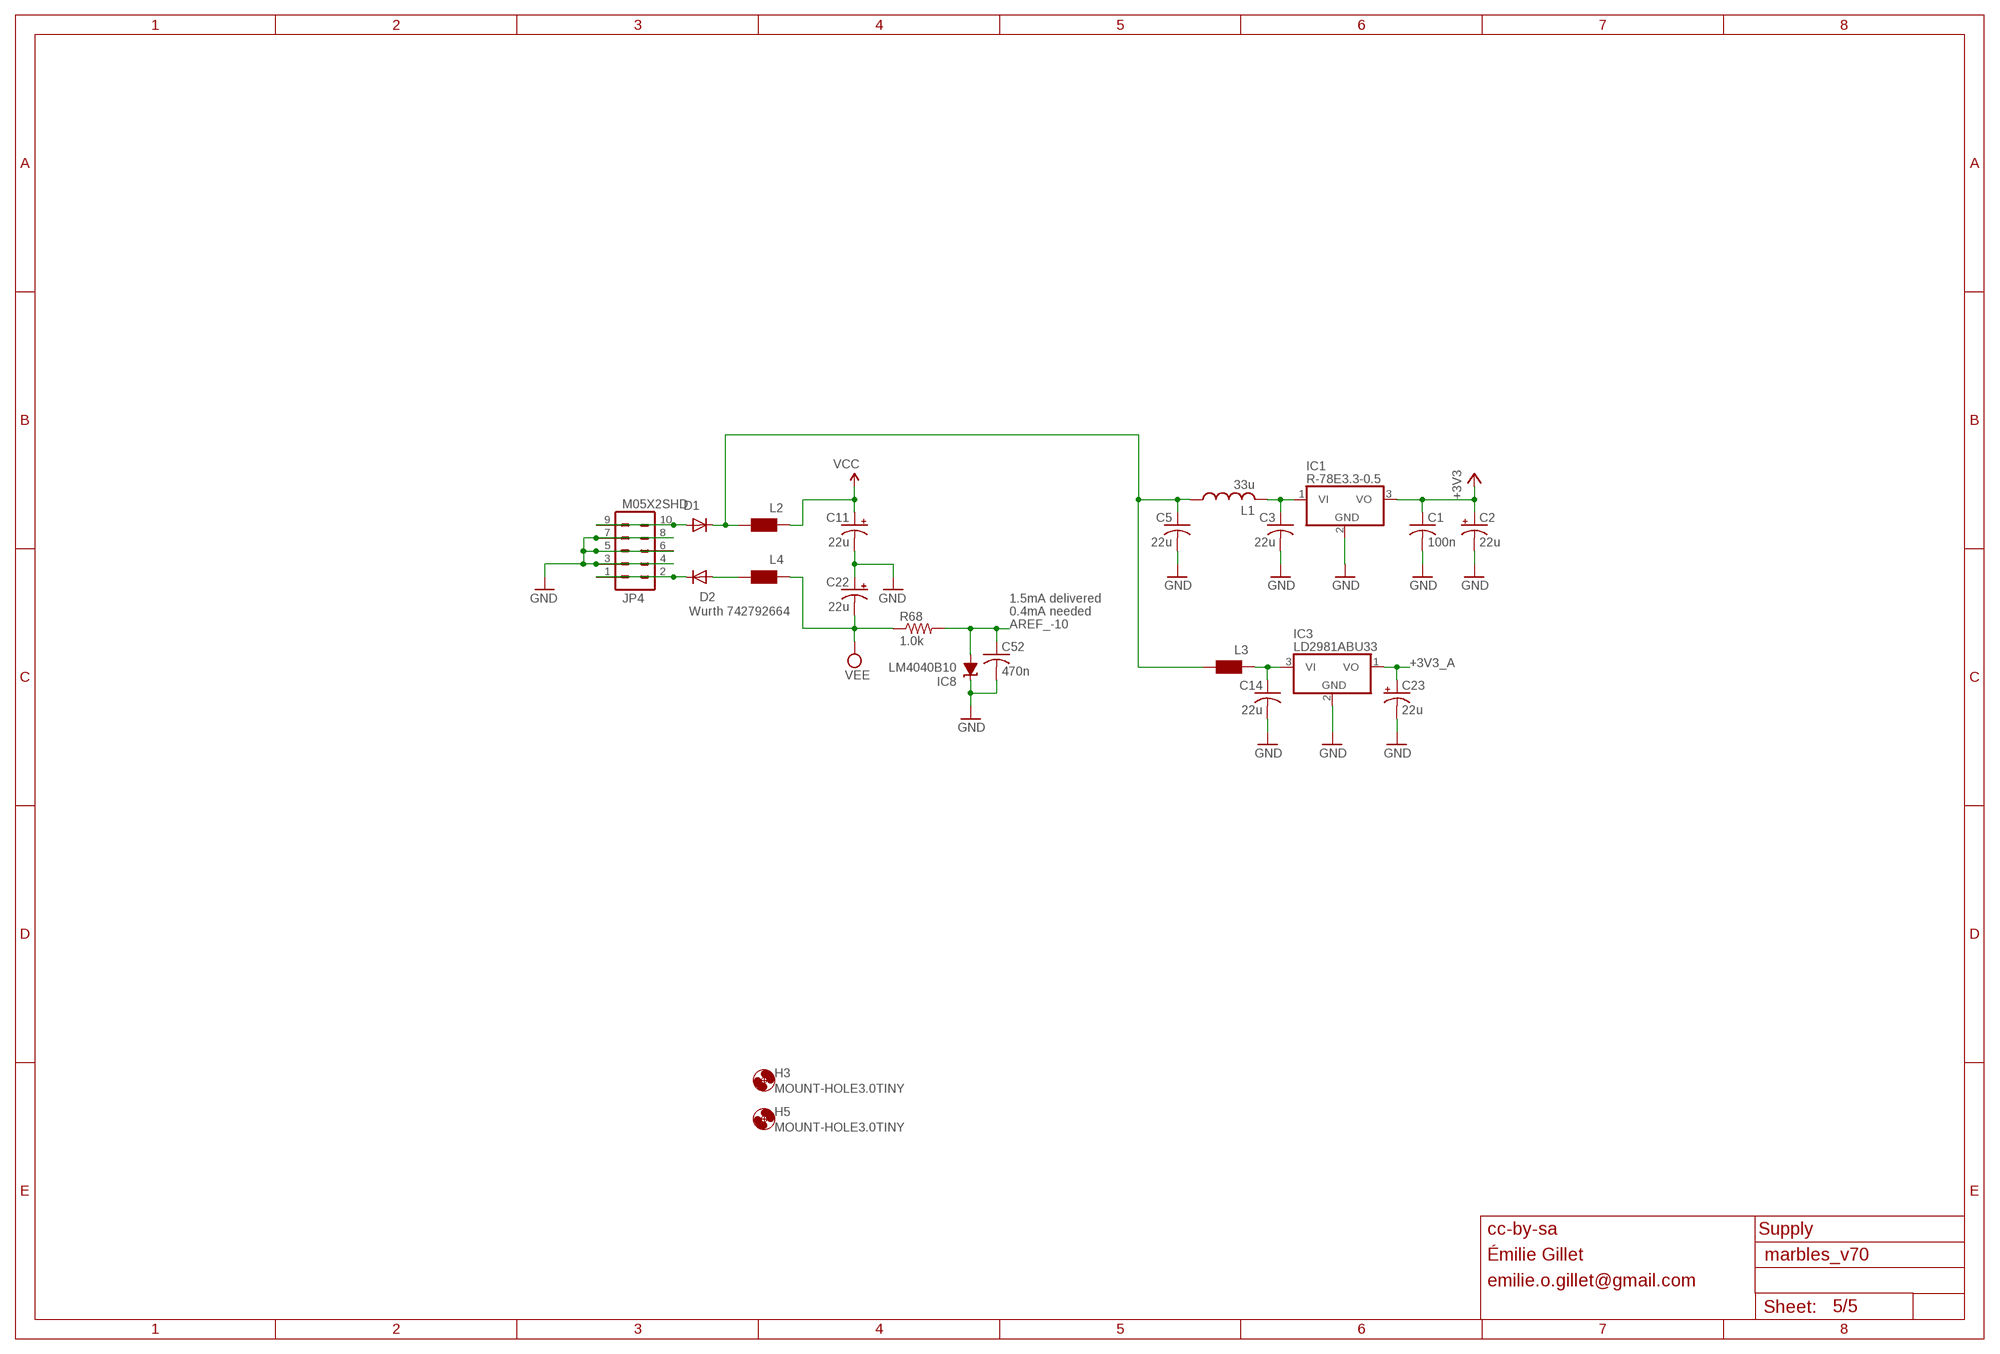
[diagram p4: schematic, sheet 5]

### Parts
C1  100n  C-USC0402  [C0402]
C2  22u  CPOL-USC  [PANASONIC_C]
C3  22u  C-USC1206  [C1206]
C5  22u  C-USC1206  [C1206]
C11  22u  CPOL-USC  [PANASONIC_C]
C14  22u  C-USC1206  [C1206]
C22  22u  CPOL-USC  [PANASONIC_C]
C23  22u  CPOL-USC  [PANASONIC_C]
C52  470n  C-USC0402  [C0402]
D1  1N5819HW  DIODE-SOD123  [SOD123]
D2  1N5819HW  DIODE-SOD123  [SOD123]
H3  MOUNT-HOLE3.0TINY  [3,0TINY]
H5  MOUNT-HOLE3.0TINY  [3,0TINY]
IC1  R-78E3.3-0.5  WE173950378  [WE78]
IC3  LD2981ABU33  LD2981ABU  [SOT89]
IC8  LM4040B10  LM4041B12DBZ  [DBZ_R-PDSO-G3]
JP4  M05X2SHD  [2X5-SHROUDED]
L1  33u  L-USL2012C  [L2012C]
L2  WE-CBF_0603  [0603]
L3  WE-CBF_0603  [0603]
L4  WE-CBF_0603  [0603]
R68  1.0k  R-US_R0402  [R0402]

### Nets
+3V3: C1.1 C2.+ IC1.3(VO) ; also sheet 1,3
+3V3_A: C23.+ IC3.1(VO) ; also sheet 1,2,3
AREF_-10: C52.1 IC8.2(A) R68.2 ; also sheet 3
GND: C1.2 C2.- C3.2 C5.2 C11.- C14.2 C22.+ C23.- C52.2 IC1.2(GND) IC3.2(GND) IC8.1(C) JP4.3 JP4.4 JP4.5 JP4.6 JP4.7 JP4.8 ; also sheet 1,2,3,4
N$4: C14.1 IC3.3(VI) L3.1
N$6: C5.1 D1.C L1.1 L2.2 L3.2
N$10: D2.A L4.2
N$32: C3.1 IC1.1(VI) L1.2
N$56: D1.A JP4.9 JP4.10
N$64: D2.C JP4.1 JP4.2
VCC: C11.+ L2.1 ; also sheet 4
VEE: C22.- L4.1 R68.1 ; also sheet 4

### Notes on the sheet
- 1.5mA delivered
- Wurth 742792664 | 0.4mA needed
- cc-by-sa | Supply
- Émilie Gillet
- emilie.o.gillet@gmail.com

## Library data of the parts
C1 C3-C10 C12-C21 C24-C26 C28-C58 = rcl:C-US: CAPACITOR, American symbol
C2 C11 C22 C23 C27 = rcl:CPOL-US: POLARIZED CAPACITOR, American symbol
D1 D2 D4 D5 = diode:DIODE-: DIODE
D3 = diode:DIODE_2CACA-: 2 Diodes - Cathode-Anode|Cathode-Anode
F1-F3 = SparkFun:FIDUCIAL: Fiducial Alignment Points
H3 H5 = og-holes:MOUNT-HOLE: MOUNTING HOLE with drill center marker
IC1 = og-vreg:WE173950378
IC2 = og-stm32f2:STM32F20X
IC3 = og-vreg:LD2981
IC4 = og-dac:DAC8564
IC5-IC7 IC9 IC10 = og-linear:TL074: OP AMP
IC8 = texas:LM4041: PRECISION MICROPOWER SHUNT VOLTAGE REFERENCE
J1-J16 = og-pj301:PJ301_THONKICONN
JP1 = SparkFun:M04: Header 4 Standard 4-pin 0.1" header. Use with straight break away headers (SKU : PRT-00116), right angle break away headers (PRT-00553), swiss pins (PRT-00743), machine pins (PRT-00117), and female headers (PRT-00115). Molex polarized connector foot print use with SKU : PRT-08231 with associated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
JP2 = SparkFun:M02: Header 2
JP4 = og-header:M05X2: Header 5x2 Standard 10-pin dual row 0.1" header. Commonly used with AVR-ISP. Use with Spark Fun Electronics SKU: PRT-00778
L1 = og-rcl:L-US
L2-L4 = wuerth-elektronik:WE-CBF: SMD EMI Suppression Ferrite Beads
LED1-LED5 = og-leds:LED-BICOLOR-THROUGHHOLE
LED6-LED12 = og-leds:LED-BICOLOR-SHARED-THROUGHHOLE
Q1 = og-crystal:CRYSTAL: Crystal with 2 extra terminals for the metal LID (Abracon ABMM2 for example)
Q2 Q3 = transistor:*-NPN-: NPN Transistror BF959 corrected 2008.03.06
R1-R3 R5-R12 R15 R17-R19 R22-R36 R39-R87 = rcl:R-US_: RESISTOR, American symbol
R4 R13 R14 R16 R20 R21 R37 R38 = og-pots:POT_US
SW1 SW2 = og-switch:LP4OA1PBCT
SW3-SW7 = SparkFun:TAC_SWITCH: Momentary Switch Button commonly used for reset or general input. Spark Fun Electronics SKU : COM-00097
